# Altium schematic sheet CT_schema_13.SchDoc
size 385 x 278 mm
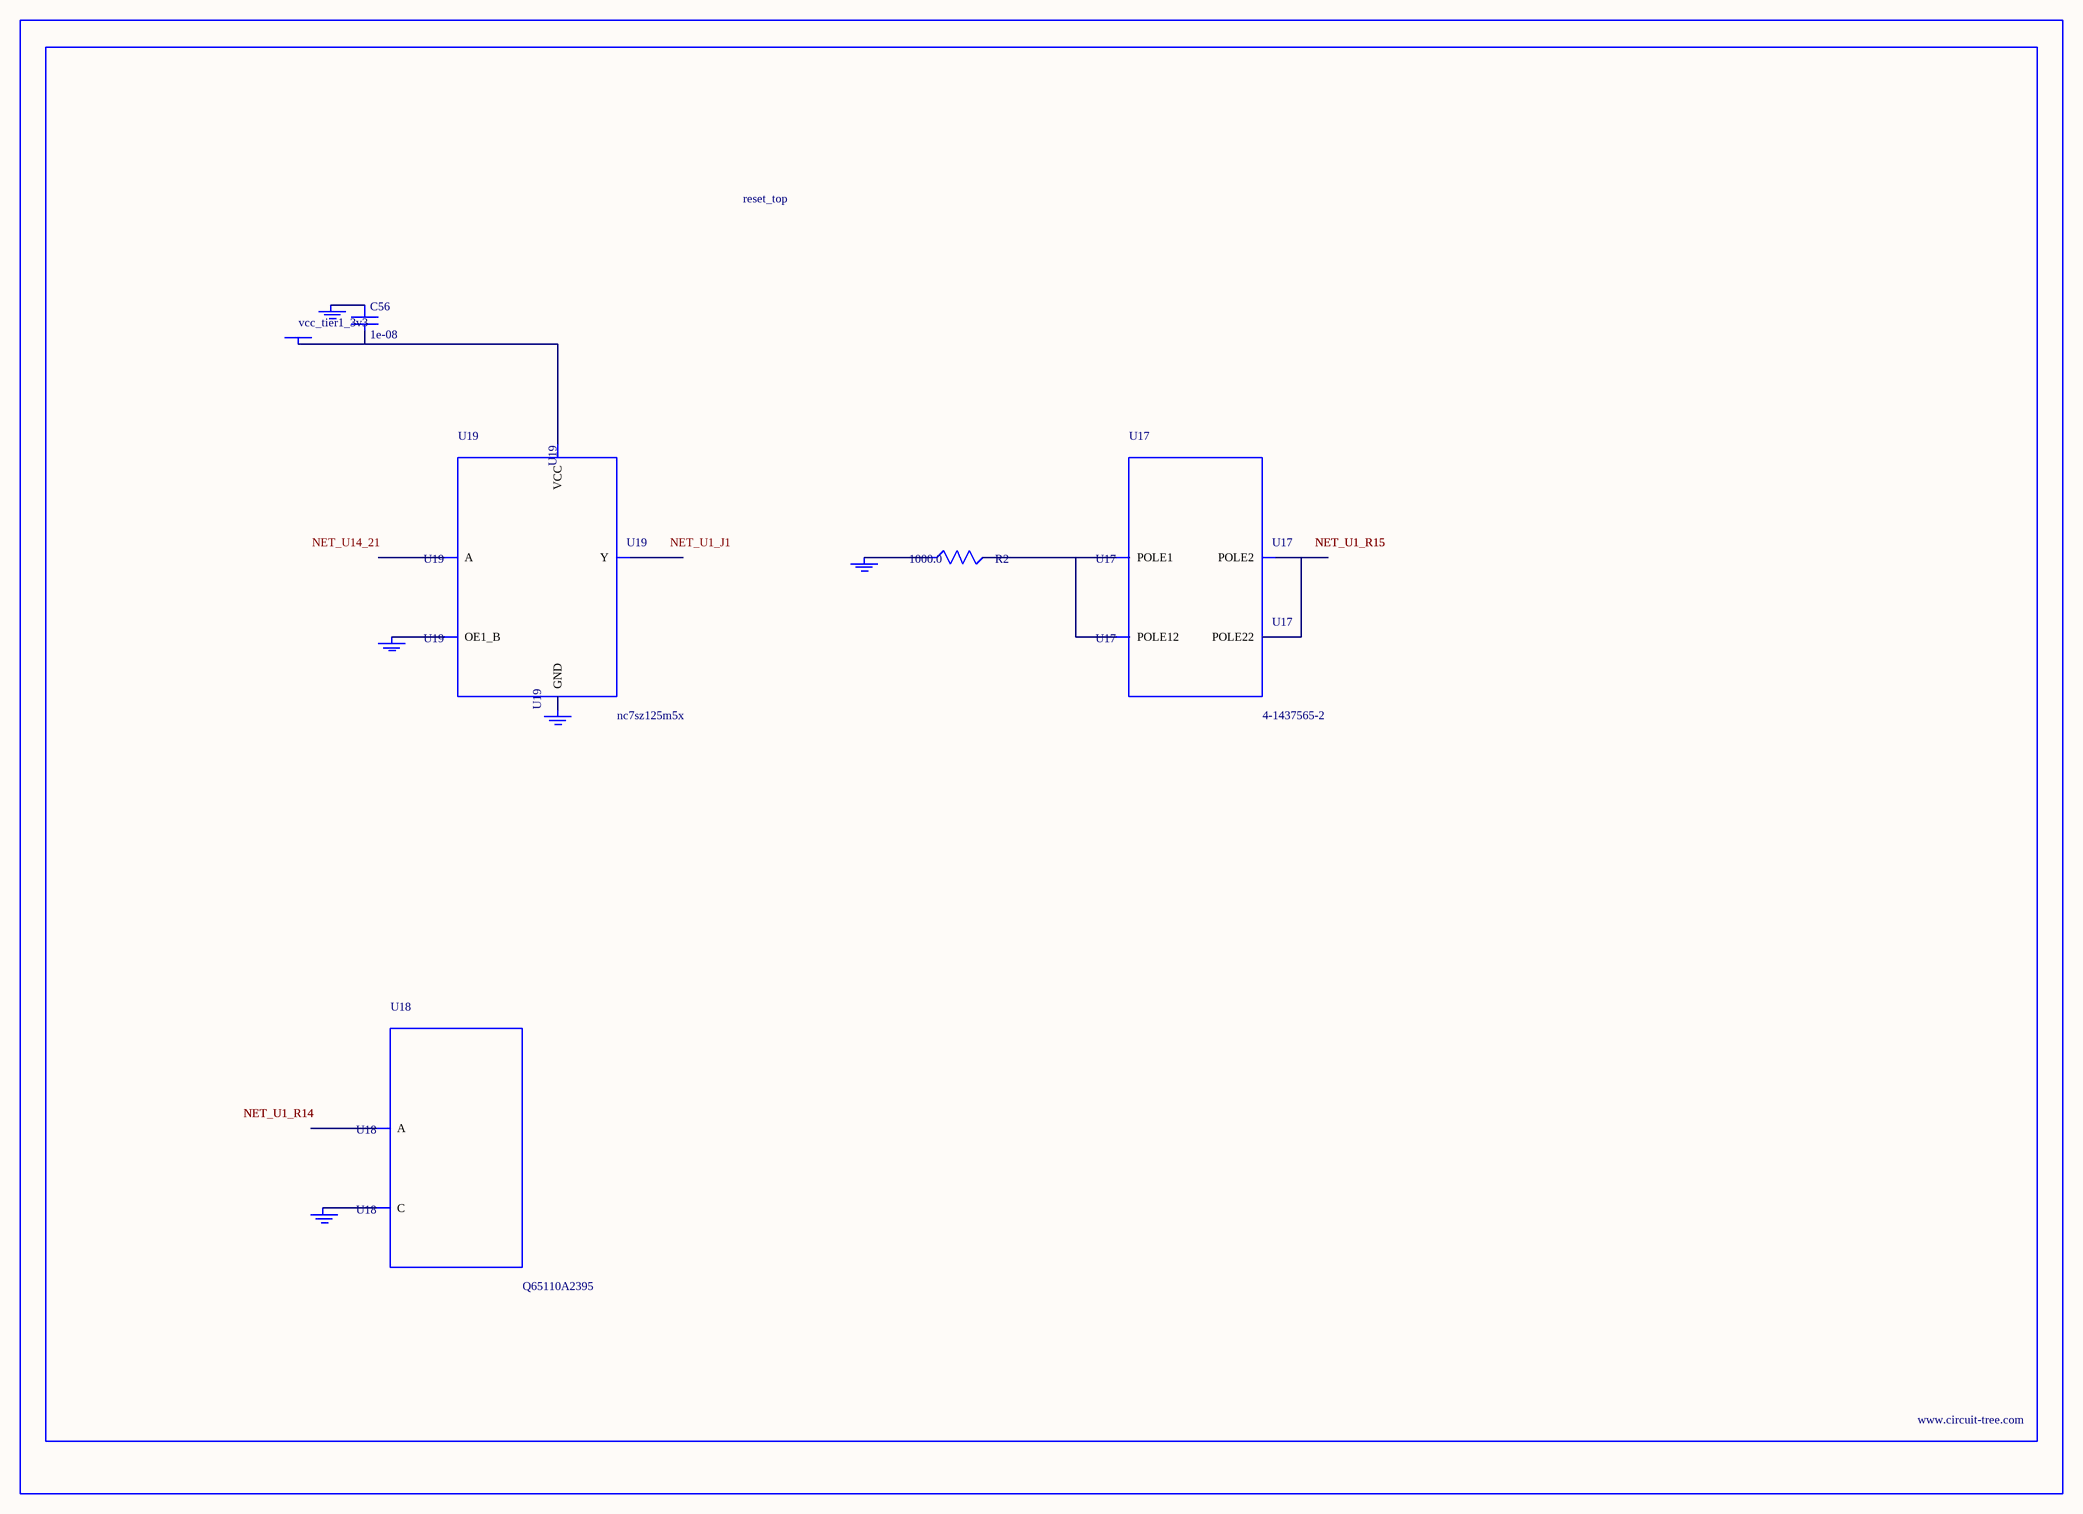
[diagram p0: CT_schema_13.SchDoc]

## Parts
BORDER12  (no value)
C56  1e-08  [C0402]
GND_INSTANCE_12_0  (no value)
GND_INSTANCE_12_1  (no value)
GND_INSTANCE_12_2  (no value)
GND_INSTANCE_12_3  (no value)
GND_INSTANCE_12_4  (no value)
POWER_INSTANCE_12_0  vcc_tier1_3v3
R2  1000.0  [R0603]
U17  4-1437565-2  [SW_4-1437565-2]
U18  Q65110A2395  [LGM67K-G1J2-24-Z]
U19  nc7sz125m5x  [NC7SZ125M5X]

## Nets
NetC56_1: C56.1 GND_INSTANCE_12_2.0(GND)
NetC56_2: C56.2 POWER_INSTANCE_12_0.0(PWR) U19.5(VCC)
NetGND_INSTANCE_12_0_0: GND_INSTANCE_12_0.0(GND) R2.1
NetGND_INSTANCE_12_1_0: GND_INSTANCE_12_1.0(GND) U18.C
NetGND_INSTANCE_12_3_0: GND_INSTANCE_12_3.0(GND) U19.1(OE1_B)
NetGND_INSTANCE_12_4_0: GND_INSTANCE_12_4.0(GND) U19.3(GND)
NetR2_2: R2.2 U17.1(POLE1) U17.2(POLE12)
NetU17_3: U17.3(POLE2) U17.4(POLE22)

Not connected (* = marked no-connect by the designer): U18 A; U19 2(A) 4(Y)

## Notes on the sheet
- Labels drawn without touching a wire or pin: NET_U1_J1, NET_U14_21

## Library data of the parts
BORDER12 = BORDER_PAGE12
C56 = C0402C103K3RAC
GND_INSTANCE_12_0-GND_INSTANCE_12_4 = GND
POWER_INSTANCE_12_0 = PWR
R2 = RC0603JR-071KL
